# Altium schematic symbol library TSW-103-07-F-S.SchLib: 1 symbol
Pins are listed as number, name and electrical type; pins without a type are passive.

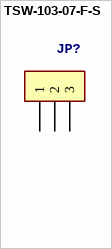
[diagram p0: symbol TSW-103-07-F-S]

## TSW-103-07-F-S
designator JP?
footprint TSW-103-07-F-S
pins: 1, 2, 3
